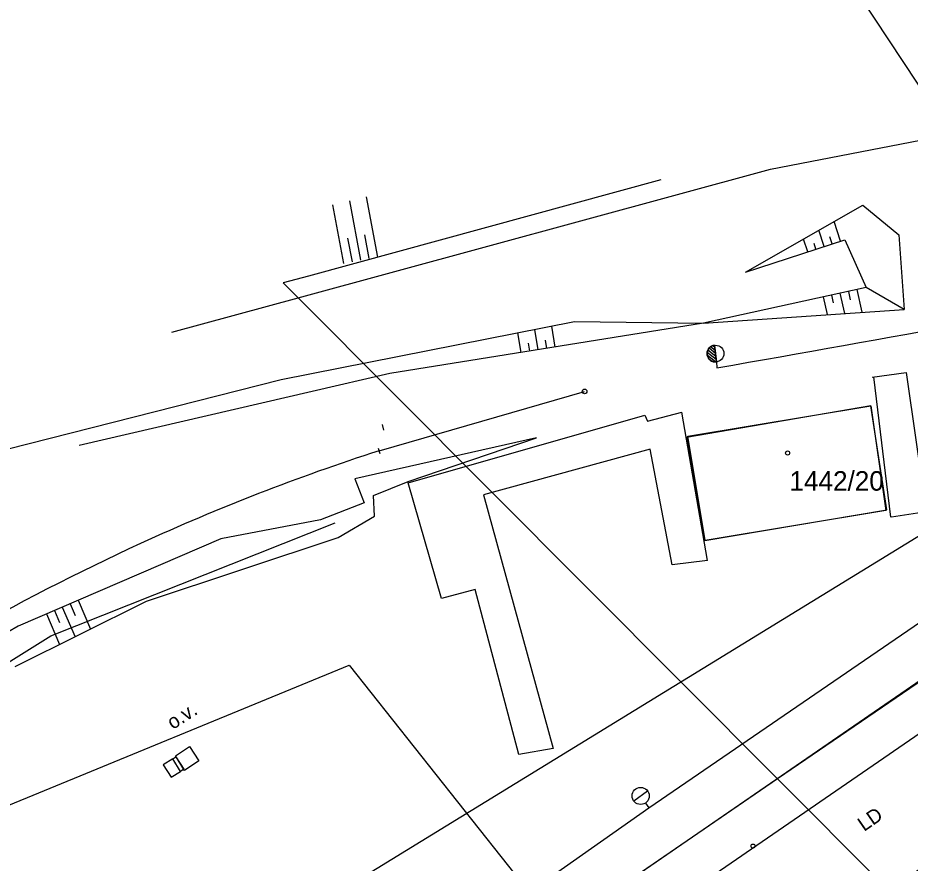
# Model space of a CAD drawing. Extents: x -469926 to -462499, y -1098642 to -1092733.
# Drawn here: x -466842 to -466764.3, y -1096249.7 to -1096176.1 of the extents above; entities that cross this region are included whole.
import ezdxf

# ---------------------------------------------------------------- set-up
doc = ezdxf.new("R2010")
doc.units = 0
for name, color, linetype in [('Vrstva 1', 7, 'Continuous'), ('Vrstva 12', 7, 'Continuous'), ('Vrstva 13', 7, 'Continuous'), ('Vrstva 14', 7, 'Continuous'), ('Vrstva 25', 7, 'Continuous'), ('Vrstva 4', 7, 'Continuous'), ('Vrstva 40', 7, 'Continuous'), ('Vrstva 42', 7, 'Continuous'), ('Vrstva 48', 7, 'Continuous'), ('Vrstva 50', 7, 'Continuous'), ('Vrstva 51', 7, 'Continuous'), ('Vrstva 6', 7, 'Continuous'), ('Vrstva 62', 7, 'Continuous'), ('Vrstva 7', 7, 'Continuous'), ('Vrstva 8', 7, 'Continuous')]:
    doc.layers.add(name, color=color, linetype=linetype)

msp = doc.modelspace()

# ---------------------------------------------------------------- linework, layer by layer
at = {"layer": 'Vrstva 1'}
for p, q in [((-466776.43, -1096189.23), (-466761.56, -1096186.36)), ((-466817.57, -1096200.43), (-466776.43, -1096189.23)), ((-466828.56, -1096203.42), (-466817.57, -1096200.43)), ((-466810.511, -1096213.764), (-466792.613, -1096208.59)), ((-466767.69, -1096209.84), (-466783.74, -1096212.59)), ((-466766.29, -1096218.91), (-466767.69, -1096209.84)), ((-466783.74, -1096212.59), (-466782.15, -1096221.56)), ((-466782.15, -1096221.56), (-466766.29, -1096218.91)), ((-466756.01, -1096228.78), (-466775.8, -1096242.32)), ((-466775.8, -1096242.32), (-466790.02, -1096252.05))]:
    msp.add_line(p, q, dxfattribs=at)
msp.add_lwpolyline([(-466826.173, -1096276.422), (-466824.664, -1096275.165), (-466816.294, -1096268.012), (-466807.229, -1096260.264), (-466805.438, -1096258.802), (-466795.147, -1096250.562), (-466787.005, -1096244.832), (-466758.566, -1096225.371)], dxfattribs=at)
for centre, radius, start, end in [((-467517.95, -1092010.264), 4260.48, 279.959625, 280.562236), ((-466754.12, -1096389.686), 184.739, 107.77315, 114.68739), ((-466744.809, -1096409.94), 207.031, 114.68739, 124.69414)]:
    msp.add_arc(centre, radius, start, end, dxfattribs=at)
at = {"layer": 'Vrstva 12'}
msp.add_lwpolyline([(-466828.485, -1096240.579), (-466828.199, -1096240.399), (-466827.511, -1096241.489), (-466827.808, -1096241.676)], close=True, dxfattribs=at)
at = {"layer": 'Vrstva 13'}
for p, q in [((-466818.86, -1096199.14), (-466817.57, -1096200.43)), ((-466818.86, -1096199.14), (-466817.57, -1096200.43)), ((-466817.57, -1096200.43), (-466775.8, -1096242.32)), ((-466817.57, -1096200.43), (-466775.8, -1096242.32)), ((-466775.8, -1096242.32), (-466766.12, -1096252.03)), ((-466775.8, -1096242.32), (-466766.12, -1096252.03))]:
    msp.add_line(p, q, dxfattribs=at)
at = {"layer": 'Vrstva 14'}
msp.add_line((-466775.189, -1096164.217), (-466754.043, -1096196.348), dxfattribs=at)
at = {"layer": 'Vrstva 25'}
for centre in [(-466774.93, -1096213.95), (-466777.94, -1096248.17)]:
    msp.add_circle(centre, 0.175, dxfattribs=at)
at = {"layer": 'Vrstva 4'}
for p, q in [((-466785.97, -1096190.18), (-466816.66, -1096198.54)), ((-466816.66, -1096198.54), (-466818.86, -1096199.14))]:
    msp.add_line(p, q, dxfattribs=at)
at = {"layer": 'Vrstva 40'}
msp.add_lwpolyline([(-466828.485, -1096240.579), (-466829.321, -1096241.087), (-466828.614, -1096242.186), (-466827.808, -1096241.676)], dxfattribs=at)
at = {"layer": 'Vrstva 42'}
for p, q in [((-466745.837, -1096210.368), (-466812.935, -1096251.501)), ((-466839.107, -1096229.868), (-466814.339, -1096220.025)), ((-466880.05, -1096255.306), (-466839.107, -1096229.868))]:
    msp.add_line(p, q, dxfattribs=at)
at = {"layer": 'Vrstva 48'}
for points in [[(-466810.624, -1096196.886), (-466811.605, -1096191.654)], [(-466813.572, -1096197.439), (-466814.529, -1096192.337)], [(-466812.098, -1096197.162), (-466813.067, -1096191.995)], [(-466770.325, -1096195.515), (-466770.885, -1096193.801)], [(-466771.751, -1096195.981), (-466772.214, -1096194.562)], [(-466812.835, -1096197.3), (-466813.221, -1096195.247)], [(-466811.361, -1096197.024), (-466811.751, -1096194.944)], [(-466773.177, -1096196.446), (-466773.543, -1096195.323)], [(-466771.038, -1096195.748), (-466771.243, -1096195.121)], [(-466772.464, -1096196.213), (-466772.63, -1096195.705)], [(-466771.102, -1096200.203), (-466770.957, -1096200.863)], [(-466770.369, -1096200.042), (-466769.984, -1096201.801)], [(-466769.637, -1096199.882), (-466769.473, -1096200.628)], [(-466768.904, -1096199.721), (-466768.471, -1096201.696)], [(-466771.834, -1096200.363), (-466771.497, -1096201.905)], [(-466796.654, -1096204.962), (-466796.939, -1096203.185)], [(-466795.173, -1096204.723), (-466795.467, -1096202.894)], [(-466798.135, -1096205.2), (-466798.412, -1096203.477)], [(-466795.913, -1096204.842), (-466796.029, -1096204.121)], [(-466797.394, -1096205.081), (-466797.506, -1096204.381)], [(-466838.102, -1096227.367), (-466836.995, -1096229.946)], [(-466837.413, -1096227.071), (-466836.977, -1096228.087)], [(-466836.724, -1096226.775), (-466835.651, -1096229.274)], [(-466839.48, -1096227.958), (-466838.339, -1096230.617)], [(-466838.791, -1096227.663), (-466838.342, -1096228.71)]]:
    msp.add_lwpolyline(points, dxfattribs=at)
at = {"layer": 'Vrstva 51'}
for p, q in [((-466861.89, -1096252.449), (-466813.115, -1096232.435)), ((-466813.115, -1096232.435), (-466788.727, -1096263.123))]:
    msp.add_line(p, q, dxfattribs=at)
at = {"layer": 'Vrstva 6'}
msp.add_line((-466753.883, -1096231.797), (-466782.171, -1096251.259), dxfattribs=at)
for points in [[(-466767.552, -1096207.355), (-466764.614, -1096206.949), (-466762.863, -1096219.08), (-466765.868, -1096219.536)], [(-466767.462, -1096207.32), (-466765.963, -1096219.536)], [(-466798.342, -1096240.191), (-466802.147, -1096225.841), (-466805.07, -1096226.623), (-466807.968, -1096216.544), (-466787.364, -1096210.65), (-466787.123, -1096211.184), (-466784.136, -1096210.409)], [(-466781.908, -1096223.306), (-466784.136, -1096210.409)], [(-466781.908, -1096223.306), (-466784.99, -1096223.678), (-466786.901, -1096213.614), (-466801.428, -1096217.605), (-466795.347, -1096239.685), (-466798.342, -1096240.191)]]:
    msp.add_lwpolyline(points, dxfattribs=at)
for points in [[(-466783.62, -1096212.474), (-466767.686, -1096209.846), (-466766.382, -1096218.966), (-466782.122, -1096221.561)], [(-466789.993, -1096252.029), (-466756.043, -1096228.672), (-466748.386, -1096239.999), (-466769.183, -1096254.113), (-466769.794, -1096253.315), (-466779.689, -1096260.076), (-466782.473, -1096256.063), (-466785.758, -1096258.26)], [(-466828.247, -1096240.323), (-466827.013, -1096239.516), (-466826.207, -1096240.75), (-466827.452, -1096241.583)]]:
    msp.add_lwpolyline(points, close=True, dxfattribs=at)
at = {"layer": 'Vrstva 62'}
for p, q in [((-466796.8, -1096212.629), (-466812.629, -1096216.192)), ((-466807.985, -1096216.425), (-466796.8, -1096212.629)), ((-466812.629, -1096216.192), (-466811.819, -1096218.299)), ((-466811.008, -1096217.64), (-466807.985, -1096216.425)), ((-466810.898, -1096219.44), (-466811.008, -1096217.64)), ((-466811.819, -1096218.299), (-466815.612, -1096219.777)), ((-466814.061, -1096221.318), (-466810.898, -1096219.44)), ((-466815.612, -1096219.777), (-466824.28, -1096221.435)), ((-466824.28, -1096221.435), (-466841.941, -1096229.014)), ((-466830.774, -1096226.839), (-466814.061, -1096221.318)), ((-466842.214, -1096232.552), (-466830.774, -1096226.839)), ((-466841.941, -1096229.014), (-466854.728, -1096236.45))]:
    msp.add_line(p, q, dxfattribs=at)
for points in [[(-466778.601, -1096198.218), (-466768.373, -1096192.364), (-466765.255, -1096194.959), (-466764.78, -1096201.442), (-466768.089, -1096199.542)], [(-466778.601, -1096198.218), (-466769.953, -1096195.393), (-466768.089, -1096199.542), (-466782.261, -1096202.648), (-466809.586, -1096207.04), (-466836.632, -1096213.289)], [(-466782.261, -1096202.648), (-466764.78, -1096201.442)], [(-466842.928, -1096213.63), (-466819.031, -1096207.559), (-466793.485, -1096202.502), (-466782.261, -1096202.648)]]:
    msp.add_lwpolyline(points, dxfattribs=at)
at = {"layer": 'Vrstva 8'}
for p, q in [((-466781.212, -1096205.287), (-466781.774, -1096204.833)), ((-466781.24, -1096205.023), (-466781.635, -1096204.704)), ((-466781.268, -1096204.76), (-466781.453, -1096204.609)), ((-466781.135, -1096206.026), (-466781.288, -1096204.57)), ((-466781.288, -1096204.57), (-466781.135, -1096206.026)), ((-466781.157, -1096205.814), (-466781.933, -1096205.186)), ((-466781.191, -1096206.028), (-466781.929, -1096205.431)), ((-466781.184, -1096205.551), (-466781.874, -1096204.992)), ((-466781.135, -1096206.026), (-466781.135, -1096206.026)), ((-466781.134, -1096206.026), (-466781.082, -1096206.538)), ((-466810.238, -1096211.473), (-466810.118, -1096211.957)), ((-466810.582, -1096213.524), (-466810.44, -1096214.004)), ((-466788.337, -1096244.237), (-466787.124, -1096243.376)), ((-466787.294, -1096244.424), (-466787.005, -1096244.832)), ((-466787.005, -1096244.832), (-466787.005, -1096244.832))]:
    msp.add_line(p, q, dxfattribs=at)
for centre, radius in [((-466781.212, -1096205.295), 0.731), ((-466792.613, -1096208.59), 0.2), ((-466787.729, -1096243.807), 0.745)]:
    msp.add_circle(centre, radius, dxfattribs=at)
msp.add_arc((-466781.211, -1096205.298), 0.732, 96.01317, 275.97402, dxfattribs=at)

# ---------------------------------------------------------------- texts
at = {"layer": 'Vrstva 50'}
msp.add_text('1442/20', height=1.7, dxfattribs=at).set_placement((-466774.767, -1096217.23))
at = {"layer": 'Vrstva 7'}
for s, rotation, p in [('o.v.', 32.39984, (-466828.48, -1096238.065)), ('LD', 34.69147, (-466768.275, -1096246.947))]:
    msp.add_text(s, height=1.25, rotation=rotation, dxfattribs=at).set_placement(p)

doc.saveas('drawing.dxf')
